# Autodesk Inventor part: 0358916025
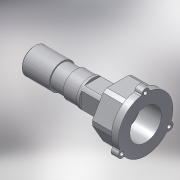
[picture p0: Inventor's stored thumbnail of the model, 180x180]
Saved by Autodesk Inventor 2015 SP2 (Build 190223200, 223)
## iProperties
Created: 2017-01
Part Number: 0358916025
Material: PVC-Piping
Description: SERIES 1 FREE NUT ADAPTOR 25-1" (KIT 2 UNITS)
Document SubType Name: Modeling
Designer: Кирилл
Mass: 43.954 g
Surface Area: 139.205 cm^2
Volume: 31.3957 cm^3
Density: 1.4 g/cm^3
Appearance: Smooth - White
Author: KIM
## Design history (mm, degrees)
derived "0358916.ipt"
feature "Solid1::0358916.ipt"
tag "TaggingFeature1"
body "Solid1"
other parameters: "d1" = 30.291, "d2" = 25, "d3" = 22.5, "d4" = 26.25, "d6" = 22.5, "d7" = 5.625, "d8" = 49, "d9" = 5.625, "d10" = 15, "d11" = 22.5, "d13" = 1, "d14" = 2, "d17" = 0, "d19" = 360 deg, "d21" = 6.25, "d22" = 45 deg, "d30" = 0, "d31" = 2, "d34" = 7.5, "d36" = 0, "d37" = 3.75, "d39" = 0, "d41" = 360 deg, "d43" = 1.25, "d44" = 0.75, "G_" = 30.291, "d_" = 25
